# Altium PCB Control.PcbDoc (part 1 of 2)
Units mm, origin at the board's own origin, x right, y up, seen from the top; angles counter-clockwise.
Board outline 30.5 x 82 mm, 2 copper layers (Top Layer, Bottom Layer), stack 1.071 mm thick; 79 components, 65 nets, 365 pads, 467 vias.
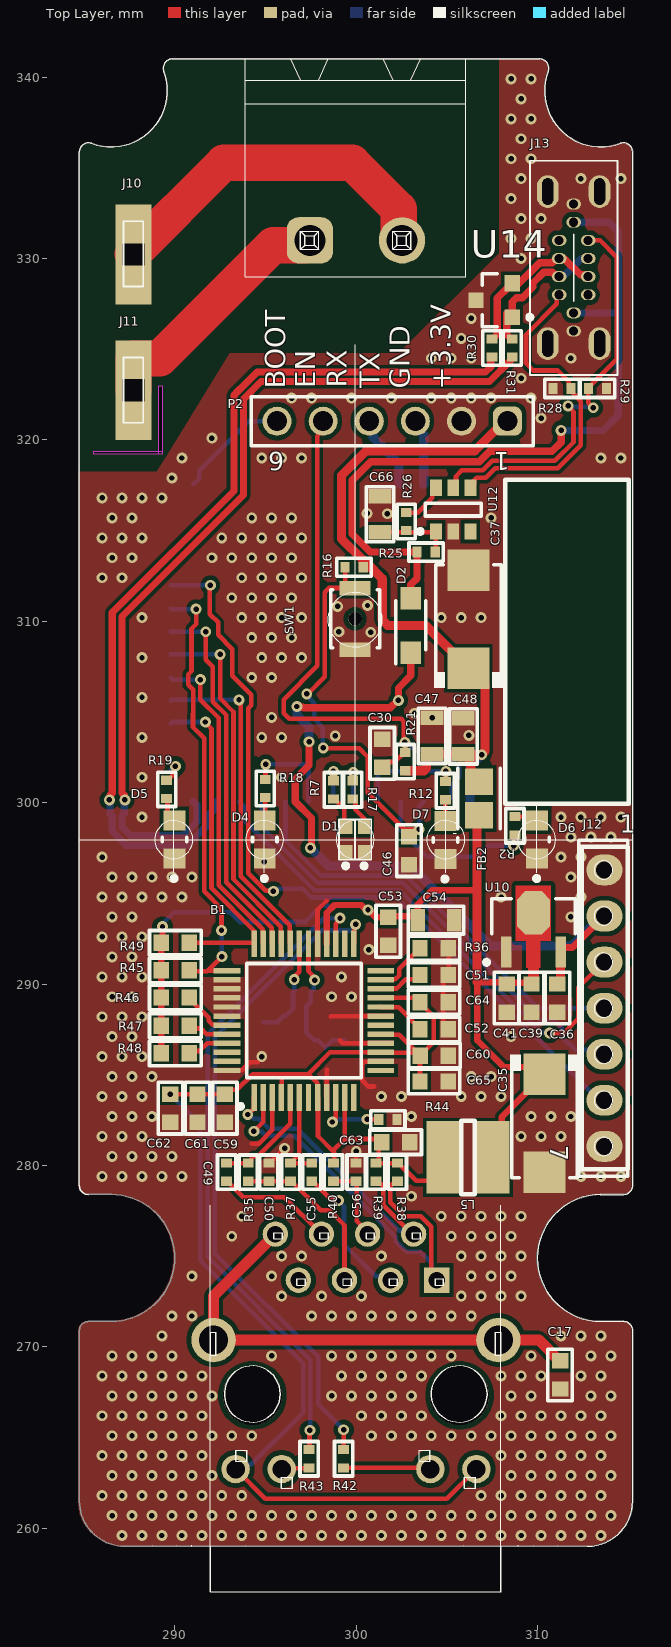
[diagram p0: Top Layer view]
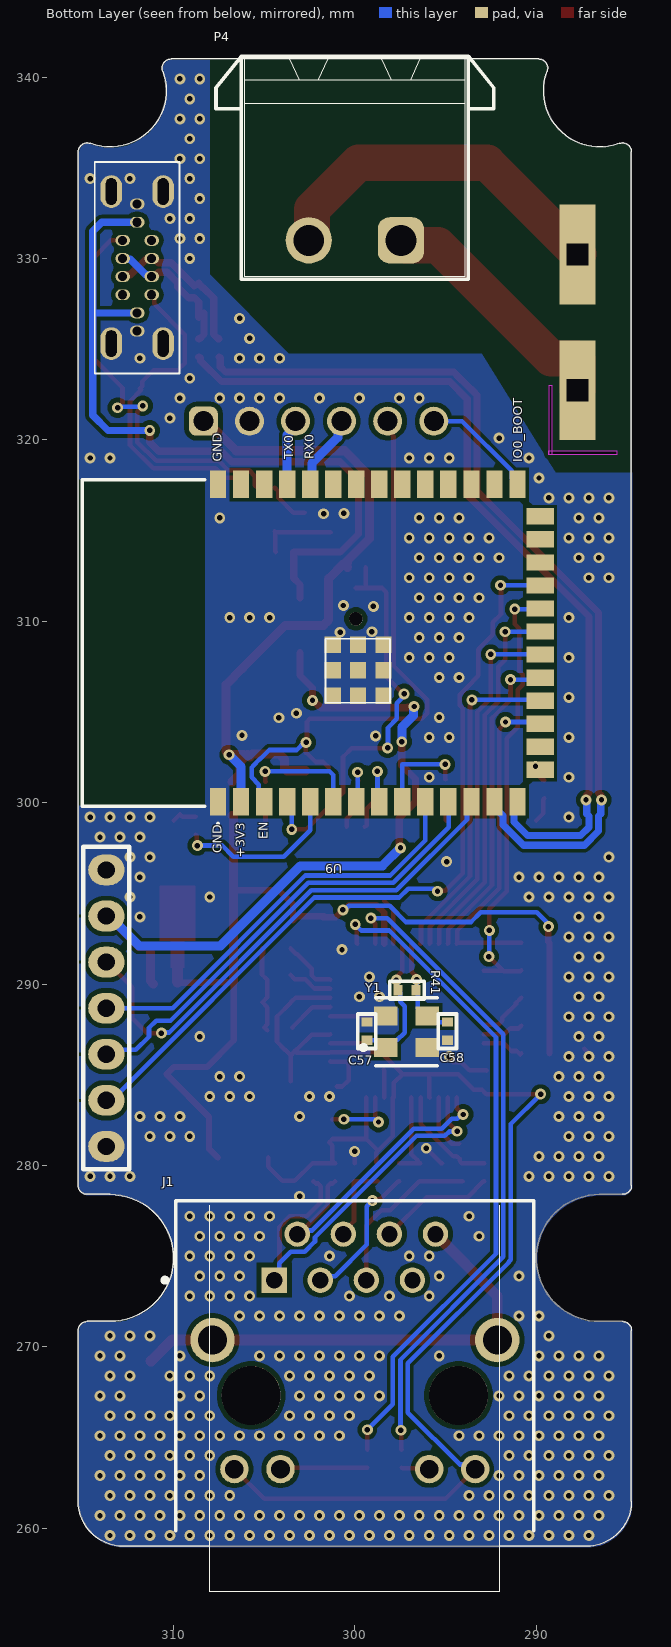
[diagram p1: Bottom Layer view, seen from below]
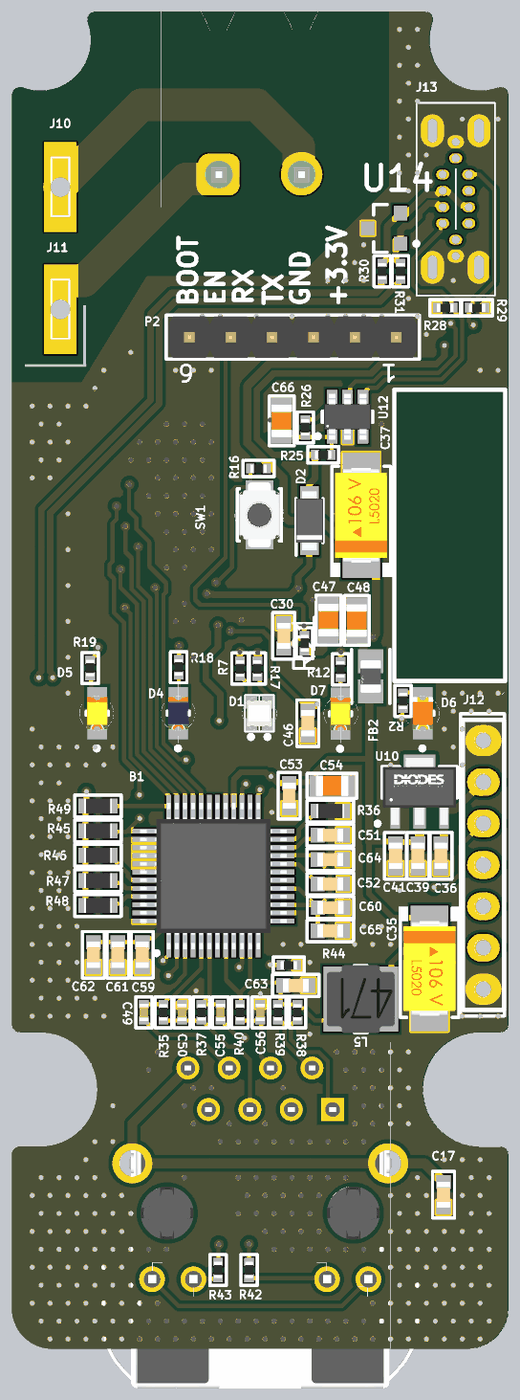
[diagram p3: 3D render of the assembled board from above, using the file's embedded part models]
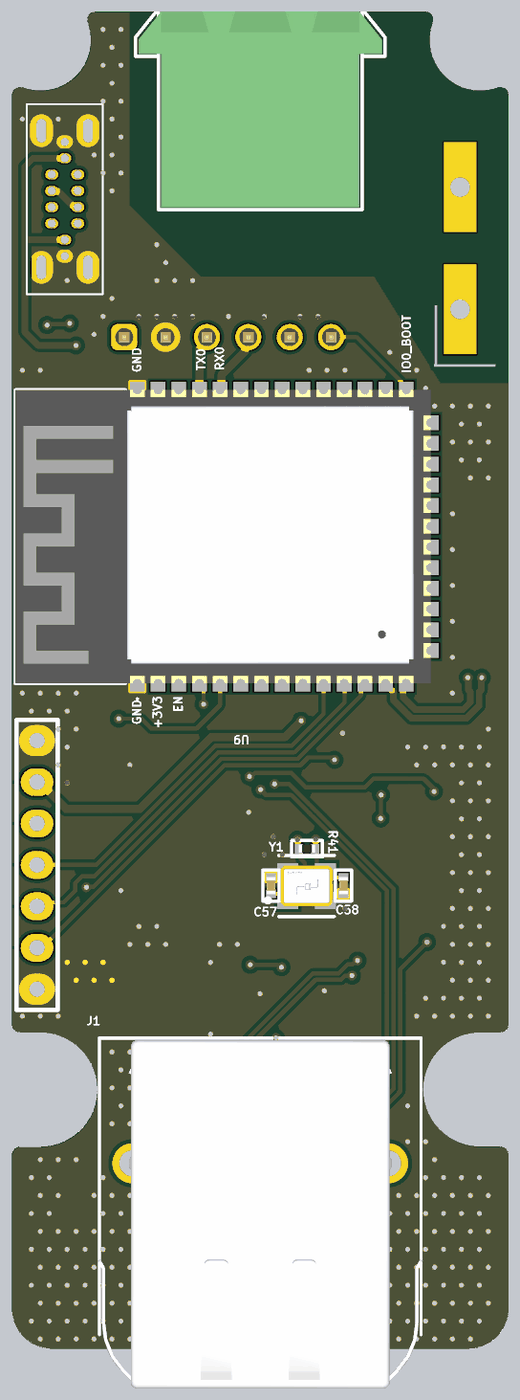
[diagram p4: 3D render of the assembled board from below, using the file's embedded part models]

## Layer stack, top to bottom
Top Solder: solder mask 0.0102, Solder Resist, Dk 3.5
Top Layer: signal copper 0.0356
Dielectric 1: dielectric 1, FR-4, Dk 4.8
Bottom Layer: signal copper 0.0356
Bottom Solder: solder mask 0.0102, Solder Resist, Dk 3.5

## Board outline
284.75,270.9 cw(c285.25,270.9) 285.25,271.4 286.5,271.4 ccw(c286.5,274.9) 286.5,278.4 285.25,278.4 cw(c285.25,278.9) 284.75,278.9 284.75,335.874 cw(c285.25,335.874) 285.424,336.343 ccw(c286.5,339.25) 289.407,340.326 cw(c289.876,340.5) 289.876,341 310.124,341 cw(c310.124,340.5) 310.593,340.326 ccw(c313.5,339.25) 314.576,336.343 cw(c314.75,335.874) 315.25,335.874 315.25,278.9 cw(c314.75,278.9) 314.75,278.4 313.5,278.4 ccw(c313.5,274.9) 313.5,271.4 314.75,271.4 cw(c314.75,270.9) 315.25,270.9 315.25,261.5 cw(c312.75,261.5) 312.75,259 287.25,259 cw(c287.25,261.5) 284.75,261.5
cut-out: 289.331,319.203 285.548,319.203 285.548,319.38 289.331,319.38
cut-out: 289.129,319.203 289.129,322.986 289.306,322.986 289.306,319.203

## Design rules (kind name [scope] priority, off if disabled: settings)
Clearance Clearance_DiffPairs [All] p1: gap=0.254 ignorepadtopadclearanceinfootprint=FALSE except(0.1: Arc-Arc Arc-Track Track-Track; 0.15: Arc-SMDPad Arc-THPad Track-SMDPad Track-THPad SMDPad-SMDPad; 0.2: Arc-Fill Arc-Poly Arc-Region Track-Fill Track-Poly Track-Region SMDPad-Fill SMDPad-Poly SMDPad-Region)
Clearance Clearance_1 [All] p2: gap=0.254 ignorepadtopadclearanceinfootprint=FALSE except(0.15: Arc-Arc Arc-Track Arc-SMDPad Arc-THPad Track-Track Track-SMDPad Track-THPad SMDPad-SMDPad; 0.2: Arc-Fill Arc-Poly Arc-Region Track-Fill Track-Poly Track-Region SMDPad-Fill SMDPad-Poly SMDPad-Region)
DiffPairsRouting DiffPairsRouting_2 [InDifferentialPair('TX')] p1: maxlimit=0.127 minlimit=0.127 mostfreqgap=0.127 toplayer_minwidth=0.257 toplayer_maxwidth=0.257 toplayer_prefwidth=0.257 bottomlayer_minwidth=0.257 bottomlayer_maxwidth=0.257 bottomlayer_prefwidth=0.257 impedanceprofiledriven=TRUE impedanceprofileid={17FF99D6-841A-44A6-B72D-4877BCBBE8D0} impedanceprofilevalue=100.000000 maxuncoupledlength=12.7
DiffPairsRouting DiffPairsRouting_1 [InDifferentialPair('D')] p2: maxlimit=0.127 minlimit=0.127 mostfreqgap=0.127 toplayer_minwidth=0.403 toplayer_maxwidth=0.403 toplayer_prefwidth=0.403 bottomlayer_minwidth=0.403 bottomlayer_maxwidth=0.403 bottomlayer_prefwidth=0.403 impedanceprofiledriven=TRUE impedanceprofileid={67F76D44-EA98-4726-9E93-E288EFCD1E18} impedanceprofilevalue=90.000000 maxuncoupledlength=12.7
DiffPairsRouting [InDifferentialPair('USB_D')] p3: maxlimit=0.127 minlimit=0.127 mostfreqgap=0.127 toplayer_minwidth=0.403 toplayer_maxwidth=0.403 toplayer_prefwidth=0.403 bottomlayer_minwidth=0.403 bottomlayer_maxwidth=0.403 bottomlayer_prefwidth=0.403 impedanceprofiledriven=TRUE impedanceprofileid={67F76D44-EA98-4726-9E93-E288EFCD1E18} impedanceprofilevalue=90.000000 maxuncoupledlength=12.7
HoleSize [All] p1: absolutevalues=TRUE maxlimit=4 minlimit=0.025 maxpercent=80.000 minpercent=20.000
Length USB_Max_Lenght [InNet('D_P')] p1: maxlimit=100 minlimit=0
MatchedLengths USB [InDifferentialPair('USB_D')] p1: tolerance=25.4 checknetsindiffpair=FALSE checkdiffpairvsdiffpair=TRUE checkxsignals=TRUE checkothers=TRUE
MinimumSolderMaskSliver [All] p1: minsoldermaskwidth=0.15
PlaneClearance [All] p1: clearance=0.25
PlaneConnect [All] p1: planeconnectstyle=Direct reliefexpansion=0.508 reliefentries=4 reliefconductorwidth=0.254 reliefairgap=0.254
PolygonConnect [All] p1: connectstyle=Direct reliefconductorwidth=0.254 reliefentries=4 polygonreliefangle="90 Angle" airgapwidth=0.254
RoutingVias [All] p1: holewidth=0.3 width=0.6 viastyle="Through Hole" minholewidth=0.3 minwidth=0.6 maxholewidth=0.4 maxwidth=0.8
SilkToSilkClearance [All] p1: silktosilkclearance=0.1
SilkToSolderMaskClearance [IsPad] p1: minsilkscreentomaskgap=0.1 clearancetoexposedcopper=TRUE
SolderMaskExpansion [All] p1: expansion=0.102 istentingtop=FALSE
SupplyNets "Schematic Supply Nets_2" [InNet('V_BUS')] p1: voltage=0.000
SupplyNets "Schematic Supply Nets_12" [InNet('G')] p2: voltage=0.000
SupplyNets "Schematic Supply Nets_11" [InNet('+3v3')] p3: voltage=0.000
SupplyNets "Schematic Supply Nets_10" [InNet('VCC_2')] p4: voltage=0.000
SupplyNets "Schematic Supply Nets_7" [InNet('+3V3_MCU')] p5: voltage=0.000
SupplyNets "Schematic Supply Nets_6" [InNet('GND_PE')] p6: voltage=0.000
Width [All] p1: maxlimit=2 minlimit=0.254 preferedwidth=0.5 minimp=50.000000 maximp=50.000000 favimp=50.000000
23 further rules are at their usual default settings.

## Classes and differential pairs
differential pair RXN: +RXN_P -RXN_N
differential pair D: +D_P -D_N
differential pair USB_D: +USB_D_P -USB_D_N
differential pair TX: +TX_P -TX_N
differential pair RX: +RX_P -RX_N

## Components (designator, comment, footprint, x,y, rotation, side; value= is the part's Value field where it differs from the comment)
B1 "W5500" QFP50P900X900X160-48N 297.129,287.985 r90 top
C17 "22nF" CAP-0603 311.252,268.453 r90 top
C30 "2.2uF" CAP-0603 301.447,302.717 r270 top
C35 "100uF 16V" CAP-TAN-C 310.388,282.321 r270 top
C36 "0.1uF" CAP-0603 311.099,289.23 r90 top
C37 "100uF_16V" CAP-TAN-C 306.2,310.109 r90 top
C39 "2.2uF" CAP-0603 309.677,289.23 r90 top
C41 "0.1uF" CAP-0603 308.305,289.23 r90 top
C46 "0.1uF" CAP-0603 302.92,297.358 r90 top
C47 "10uF" CAP-0805 304.19,303.682 r270 top
C48 "0.1uF" CAP-0805 305.918,303.657 r270 top
C49 "6.8nF" CAP-0402 292.862,279.629 r90 top
C50 "10nF" CAP-0402 295.199,279.629 r270 top
C51 "10nF" CAP-0603 304.303,290.5 r0 top locked
C52 "4.7uF" CAP-0603 304.303,287.505 r0 top locked
C53 "0.1uF" CAP-0603 301.777,292.913 r90 top
C54 "10uF" CAP-0805 304.409,293.523 r180 top
C55 "6.8nF" CAP-0402 297.561,279.629 r90 top
C56 "22nF" CAP-0402 299.999,279.629 r270 top
C57 "18pF" CAP-0402 299.339,287.401 r270 bottom
C58 "18pF" CAP-0402 294.894,287.401 r90 bottom
C59 "0.1uF" CAP-0603 292.76,283.159 r90 top
C60 "0.1uF" CAP-0603 304.317,286.055 r180 top
C61 "0.1uF" CAP-0603 291.262,283.159 r90 top
C62 "0.1uF" CAP-0603 289.763,283.159 r90 top
C63 "0.1uF" CAP-0603 302.184,281.28 r180 top
C64 "0.1uF" CAP-0603 304.303,289.001 r180 top locked
C65 "10uF" CAP-0603 304.303,284.632 r180 top locked
C66 "1uF 50V" CAP-0805 301.32,315.9 r270 top
D1 "1615 RED-GREEN" LED_Bicolor_1615 299.949,297.967 r0 top
D2 "MBR140SFT1G" SODFL3616X98N 303.022,309.778 r90 top
D4 "LED BLUE" LED_BLUE 294.97,297.967 r90 top
D5 "LED YELLOW" LED_YELLOW 289.992,297.967 r90 top
D6 "LED RED" LED_RED 309.982,297.967 r90 top
D7 "LED GREEN" LED_GREEN 304.927,297.942 r90 top
FB2 "BLM21PG221SN1D" FP-BLM21-0_2-t0_85-e0_5-IPC_A 306.781,300.228 r270 top
J1 "HR911105A" RJ-45 300,267.25 r180 bottom locked
J10 "1.2x3.7mm" Pad_conn_1.2x3.7mm#1 287.68,330.251 r90 top locked
J11 "1.2x3.7mm" Pad_conn_1.2x3.7mm#2 287.655,322.707 r90 top locked
J12 "2.54 x 7_male_25mm" 2.54_Connector_x7_male_30mm 313.7,288.671 r270 top locked
J13 "Type-C_16p" "Type-C 16p vertical" 312,329.5 r90 top locked
L5 "33uH" Coil_4.5x4.5_mm 306.172,280.441 r180 top
P2 "61300611121" 61300611121 302,321.031 r180 top
P4 "691305540002" 691305540002 300,335 r0 bottom locked
R2 "330" RES-0402 308.762,298.729 r270 top
R7 "330" RES-0402 298.755,300.711 r90 top
R12 "330" RES-0402 304.927,300.66 r90 top
R16 "10K" RES-0402 299.898,312.979 r0 top
R17 "330" RES-0402 299.822,300.711 r90 top
R18 "330" RES-0402 294.996,300.787 r90 top
R19 "330" RES-0402 289.56,300.736 r90 top
R21 "100K" RES-0402 302.717,302.26 r270 top
R25 "1K" RES-0402 303.868,313.817 r0 top
R26 "20K" RES-0402 302.768,315.493 r90 top
R28 "5.1K" RES-0402 311.353,322.834 r180 top
R29 "5.1K" RES-0402 313.309,322.834 r0 top
R30 "22R" RES-0402 307.492,325.069 r90 top
R31 "22R" RES-0402 308.61,325.069 r90 top
R35 "82R 1%" RES-0402 294.056,279.629 r270 top
R36 "10K" RES-0603 304.303,291.973 r0 top locked
R37 "82R 1%" RES-0402 296.393,279.629 r90 top
R38 "50R 1%" RES-0402 302.285,279.629 r90 top
R39 "50R 1%" RES-0402 301.092,279.629 r90 top
R40 "10R 1%" RES-0402 298.755,279.629 r270 top
R41 "1M" RES-0402 297.129,289.662 r0 bottom
R42 "510" RES-0402 299.314,263.83 r90 top
R43 "510" RES-0402 297.409,263.83 r90 top
R44 "12.4К" RES-0402 301.752,282.524 r180 top
R45 "10K" RES-0603 290.043,290.754 r0 top
R46 "10K" RES-0603 290.043,289.255 r0 top
R47 "10K" RES-0603 290.043,287.706 r0 top
R48 "10K" RES-0603 290.043,286.182 r0 top
R49 "10K" RES-0603 290.043,292.278 r0 top
SW1 "B3U-1000P" FP-B3U-1000P-B-MFG 299.949,310.134 r270 top
U9 "ESP32-S3_WROOM-1  N16R8" ESP32S3WROOM1N16R8 302.283,308.8 r90 bottom locked
U10 "AMS1117-3.3" SOT-89 309.778,293.548 r0 top
U12 "CH221K" SOT-23-6 305.359,316.154 r90 top
U14 "PESD5V0S2BT" PRKT-SOT23-3_V 307.61,327.702 r180 top
Y1 "ABM8-25.000MHZ-D1X-T" FP-ABM8 297.155,287.376 r180 bottom

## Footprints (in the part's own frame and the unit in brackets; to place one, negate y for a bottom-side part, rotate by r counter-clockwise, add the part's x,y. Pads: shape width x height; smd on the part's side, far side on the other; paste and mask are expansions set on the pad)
2.54_Connector_x7_male_30mm [mm] "2.54_Connector_x7_male_30mm"
  oval 1.7x2 hole 0.95: 1(-7.62,0) 2(-5.08,0) 3(-2.54,0) 4(0,0) 5(2.54,0) 6(5.08,0) 7(7.62,0)
  silkscreen extent -8.89,-1.27 8.89,1.27, body extent -8.89,-1.27 8.89,1.27, height 2
61300611121 [mm] "Pin Header, pitch 2.54 mm, THT, Vertical, single row, 6p"
  rrect50% 1.6x1.6 hole 1.1: 1(-6.35,0)
  round 1.6 hole 1.1: 2(-3.81,0) 3(-1.27,0) 4(1.27,0) 5(3.81,0) 6(6.35,0)
  silkscreen extent -7.77,-1.35 7.77,1.35, body extent -7.62,-1.27 7.62,1.27, height 8.57
691305540002 [mm] "5,08mm - PCB Header Horizontal Entry with Plastic Latches - 02p"
  rrect50% 2.55x2.55 hole 1.7: 1(-2.54,4)
  round 2.55 hole 1.7: 2(2.54,4)
  silkscreen extent -7.65,-6.15 7.65,6.15, body extent -7.48,-6 7.48,6, height 8.63
CAP-0402 [mm]
  rect 0.5x0.6 smd: 1(-0.5,0) 2(0.5,0)
  silkscreen extent -0.95,-0.5 0.95,0.5, body extent -0.52,-0.27 0.53,0.28, height 0.55
CAP-0603 [mm]
  rect 0.85x0.9 smd: 1(-0.775,0) 2(0.775,0)
  silkscreen extent -1.43,-0.67 1.43,0.67, body extent -0.8,-0.4 0.8,0.4, height 0.8
CAP-0805 [mm]
  rect 0.8x1.25 smd mask+0.015: 1(-1,0) 2(1,0)
  silkscreen extent -1.52,-0.76 1.52,0.76, body extent -1,-0.62 1,0.63, height 0.8
CAP-TAN-C [mm]
  rect 2.3x2.3 smd: 1(-2.7,0) 2(2.7,0)
  silkscreen extent -3.8,-1.9 3,1.9, body extent -2.9,-1.6 2.9,1.6, height 2.6
Coil_4.5x4.5_mm [mm]
  rect 1.8x4 smd: 1(-1.397,0) 2(1.397,0)
  silkscreen extent -0.38,-2.03 0.38,2.03, body extent -2.07,-2.07 2.07,2.07, height 2.8
ESP32S3WROOM1N16R8 [mm]
  rect 1.5x0.9 smd: 1(-8.75,5.26) 2(-8.75,3.99) 3(-8.75,2.72) 4(-8.75,1.45) 5(-8.75,0.18) 6(-8.75,-1.09) 7(-8.75,-2.36) 8(-8.75,-3.63) 9(-8.75,-4.9) 10(-8.75,-6.17) 11(-8.75,-7.44) 12(-8.75,-8.71) 13(-8.75,-9.98) 14(-8.75,-11.25) 27(8.75,-11.25) 28(8.75,-9.98) 29(8.75,-8.71) 30(8.75,-7.44) 31(8.75,-6.17) 32(8.75,-4.9) 33(8.75,-3.63) 34(8.75,-2.36) 35(8.75,-1.09) 36(8.75,0.18) 37(8.75,1.45) 38(8.75,2.72) 39(8.75,3.99) 40(8.75,5.26)
  rect 0.9x1.5 smd: 15(-6.985,-12.5) 16(-5.715,-12.5) 17(-4.445,-12.5) 18(-3.175,-12.5) 19(-1.905,-12.5) 20(-0.635,-12.5) 21(0.635,-12.5) 22(1.905,-12.5) 23(3.175,-12.5) 24(4.445,-12.5) 25(5.715,-12.5) 26(6.985,-12.5)
  rect 0.9x0.9 smd: 41(-1.5,-2.46) 42(-2.9,-1.06) 43(-2.9,-2.46) 44(-2.9,-3.86) 45(-1.5,-3.86) 46(-0.1,-3.86) 47(-0.1,-2.46) 48(-0.1,-1.06) 49(-1.5,-1.06)
  silkscreen extent -10,5.21 9,12.75, body extent -9,-12.75 9,12.75, height 3.25
FP-ABM8 [mm] "FP-ABM8"
  rect 1.3x1.05 smd paste+0 mask+0: 1(-1.15,-0.875) 2(1.15,-0.875) 3(1.15,0.875) 4(-1.15,0.875)
  silkscreen extent -2.5,-1.88 1.7,1.88, body extent -1.6,-1.25 1.6,1.25, height 0.8
FP-B3U-1000P-B-MFG [mm]
  rect 0.8x1.7 smd paste+0 mask+0: 1(-1.7,0) 2(1.7,0)
  round 0.75 hole 0.75 unplated paste-2539.97 mask+0: ""(0,0)
  silkscreen extent -1.6,-1.35 1.6,1.35, body extent -2.2,-1.45 2.2,1.45, height 0.25
FP-BLM21-0_2-t0_85-e0_5-IPC_A [mm]
  rect 1.455x1.556 smd paste+0 mask+0: 1(-0.926,0) 2(0.926,0)
  silkscreen extent -1.65,-1.18 1.65,1.18, body extent -1,-0.63 1,0.63, height 1.05
LED_Bicolor_1615 [mm] "LED_Bicolor_1615"
  rect 0.7x0.8 smd mask+0: 1(-0.5,0.7) 2(0.5,0.7) 3(0.5,-0.7) 4(-0.5,-0.7)
  silkscreen extent -0.89,-1.57 0.89,1.12, body extent -0.75,-0.8 0.75,0.8, height 0.55
LED_BLUE [mm]
  rect 1.1x1.2 smd paste+0 mask+0: 1(1.05,0) 2(-1.05,0)
  silkscreen extent -2.27,-0.67 0.13,0.67, body extent -1,-0.63 1,0.63, height 0.8
LED_GREEN [mm]
  rect 1.1x1.2 smd paste+0 mask+0: 1(1.05,0) 2(-1.05,0)
  silkscreen extent -2.27,-0.67 0.13,0.67, body extent -1,-0.63 1,0.63, height 0.8
LED_RED [mm]
  rect 1.1x1.2 smd paste+0 mask+0: 1(1.05,0) 2(-1.05,0)
  silkscreen extent -2.27,-0.67 0.13,0.67, body extent -1.7,-0.77 1.7,0.77, height 0.25
LED_YELLOW [mm]
  rect 1.1x1.2 smd paste+0 mask+0: 1(1.05,0) 2(-1.05,0)
  silkscreen extent -2.27,-0.67 0.13,0.67, body extent -1,-0.63 1,0.63, height 0.8
Pad_conn_1.2x3.7mm#1 [mm]
  rect 5.5x2 hole 1.2 square: 1(-0.025,-0.051)
Pad_conn_1.2x3.7mm#2 [mm]
  rect 5.5x2 hole 1.2 square: 1(0.026,-0.076)
PRKT-SOT23-3_V [mm] "SOT23, 3-Leads, Body 2.92x1.3mm, Pitch 0.94mm"
  rect 0.84x0.84 smd: 1(-1,0.94) 3(1,0)
  rect 0.84x0.9 smd: 2(-1,-0.94)
  silkscreen extent -2.09,-1.46 0.65,1.46, body extent -0.65,-1.46 0.65,1.46, height 1.17
QFP50P900X900X160-48N [mm]
  rect 1.475x0.3 smd: 1(-4.238,2.75) 2(-4.238,2.25) 3(-4.238,1.75) 4(-4.238,1.25) 5(-4.238,0.75) 6(-4.238,0.25) 7(-4.238,-0.25) 8(-4.238,-0.75) 9(-4.238,-1.25) 10(-4.238,-1.75) 11(-4.238,-2.25) 12(-4.238,-2.75) 25(4.238,-2.75) 26(4.238,-2.25) 27(4.238,-1.75) 28(4.238,-1.25) 29(4.238,-0.75) 30(4.238,-0.25) 31(4.238,0.25) 32(4.238,0.75) 33(4.238,1.25) 34(4.238,1.75) 35(4.238,2.25) 36(4.238,2.75)
  rect 0.3x1.475 smd: 13(-2.75,-4.238) 14(-2.25,-4.238) 15(-1.75,-4.238) 16(-1.25,-4.238) 17(-0.75,-4.238) 18(-0.25,-4.238) 19(0.25,-4.238) 20(0.75,-4.238) 21(1.25,-4.238) 22(1.75,-4.238) 23(2.25,-4.238) 24(2.75,-4.238) 37(2.75,4.238) 38(2.25,4.238) 39(1.75,4.238) 40(1.25,4.238) 41(0.75,4.238) 42(0.25,4.238) 43(-0.25,4.238) 44(-0.75,4.238) 45(-1.25,4.238) 46(-1.75,4.238) 47(-2.25,4.238) 48(-2.75,4.238)
  silkscreen extent -4.85,-3.15 3.15,3.62, body extent -4.5,-4.5 4.5,4.5, height 1.6
RES-0402 [mm]
  rect 0.5x0.6 smd: 1(-0.5,0) 2(0.5,0)
  silkscreen extent -0.95,-0.5 0.95,0.5, body extent -0.5,-0.25 0.5,0.25, height 0.35
RES-0603 [mm]
  rect 0.85x0.9 smd: 1(-0.775,0) 2(0.775,0)
  silkscreen extent -1.43,-0.67 1.43,0.67, body extent -0.85,-0.45 0.85,0.45, height 0.55
RJ-45 [mm] "RJ-45  connector"
  rect 1.4x1.4 hole 0.9 paste-2539.97 mask+0: 1(-4.445,6.425)
  round 1.4 hole 0.9 paste-2539.97 mask+0: 2(-3.175,8.965) 3(-1.905,6.425) 4(-0.635,8.965) 5(0.635,6.425) 6(1.905,8.965) 7(3.175,6.425) 8(4.445,8.965)
  round 1.57 hole 1.02 paste-2539.97 mask+0: 9(-6.64,-3.985) 10(-4.1,-3.985) 11(4.1,-3.985) 12(6.64,-3.985)
  round 2.45 hole 1.6 paste-2539.97 mask+0: 13(-7.85,3.125) 14(7.85,3.125)
  round 3.25 hole 3.25 unplated paste-2539.97 mask+0: ""(-5.715,0.075) ""(5.715,0.075)
  silkscreen extent -10.6,-7.37 9.87,10.8, body extent -10,-10.68 10,10.68, height 15.75
SODFL3616X98N [mm]
  rect 1.24x1.12 smd: 1(-1.5,0) 2(1.5,0)
  silkscreen extent -2.12,-0.82 1.35,0.82, body extent -1.8,-0.82 1.8,0.82, height 0.98
SOT-23-6 [mm] "SOT-23-6"
  rect 0.9x0.65 smd: 1(-1.2,0.95) 2(-1.2,0) 3(-1.2,-0.95) 4(1.2,-0.95) 5(1.2,0) 6(1.2,0.95)
  silkscreen extent -1.32,-1.55 0.35,1.95, body extent -1.4,-1.45 1.4,1.45, height 1.2
SOT-89 [mm]
  rect 0.58x1.73 smd paste+0 mask+0: 1(-1.5,-1.781) 3(1.5,-1.781)
  oct 1.827x2.394 smd paste+0 mask+0: 2(0,0.381)
  Top Layer region: -0.38,-2.646 -0.38,-1.146 -0.967,-1.146 -0.967,1.884 0.967,1.884 0.967,-1.146 0.38,-1.146 0.38,-2.646
  silkscreen extent -2.7,-2.47 2.3,1.15, body extent -2.4,-2.75 2.4,1.98, height 0.25
"Type-C 16p vertical" [mm] "Type-C 16p vertical"
  oval 0.6x0.8 hole 0.5: A1/B12(-3.5,0) A4/B9(-2.5,0) A5(-1.5,0.8) A6(-0.5,0.8) A7(0.5,0.8) A8(1.5,0.8) A12/B1(3.5,0) B4/A9(2.5,0) B5(1.5,-0.8) B6(0.5,-0.8) B7(-0.5,-0.8) B8(-1.5,-0.8)
  oval 1.8x1.2 hole 0.6 slot 1.462 at 0 deg: MNT1(-4.191,1.43) MNT2(-4.191,-1.43) MNT3(4.191,-1.43) MNT4(4.191,1.43)
  silkscreen extent -5.92,-2.41 5.89,2.41, body extent -6,-2.5 6,2.5, height 13.7

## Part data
B1: "Ethernet ICs 3in1 Enet Controller TCP/IP +MAC+PHY", Manufacturer_Name="Wiznet Technology"
C17 C30 C39 C41 C46 C47 C48 C49 C50 C51 C52 C53 C54 C55 C56 C57 C58 C59 C60 C61 C62 C63 C64 C65 C66: library part CAP-NON-POLAR
C35: library part CAP-POLAR, "100uF 16V  size-C"
C36: library part CAP-NON-POLAR, "0.1uF 16V"
C37: library part CAP_POL_SMD, "100uF_16V  size-C"
D1: library part "LED Bicolor", "1615 bicolor SMD LED 2 colors Red+GREEN /  / DY-S161506URUGC-T10-4T-03"
D2: "MBR140SFT1G / DIODE SCHOTTKY 40V 1A SOD123L"
D4: library part LED, "XL-2012UBC XINGLIGHT 0805 LED BLUE", Manufacturer_Name="Wurth Elektronik", Manufacturer_Part_Number=151031YS06000, Mouser Part Number=710-151031YS06000
D5: library part LED, "XL-2012UYC  XINGLIGHT 0805 LED YELLOW", Manufacturer_Name="Wurth Elektronik", Manufacturer_Part_Number=151031YS06000, Mouser Part Number=710-151031YS06000
D6: library part LED, "XL-2012SURC   XINGLIGHT  0805  LED RED", Manufacturer_Name="Wurth Elektronik", Manufacturer_Part_Number=151031YS06000, Mouser Part Number=710-151031YS06000
D7: library part LED, "XL-2012SYGC-06  XINGLIGHT  0805  LED GREEN", Manufacturer_Name="Wurth Elektronik", Manufacturer_Part_Number=151031YS06000, Mouser Part Number=710-151031YS06000
FB2: "Chip Ferrite Bead, 0805, 220Ω @ 100MHz, 0.045Ω, 25%, 2A"
J1: library part HRK1-1B72F09
J10 J11: library part Klema_15_A
J12: library part 2.54_Connector_x7_male_25mm, "2.54_Connector_x7_male_25mm"
J13: "Type-C_16p  TYPE-C16P female socket vertical plug-in patch 8.8 mm  /  / https://www.aliexpress.com/item/1005012731556882.html?spm=a2g0o.cart.0.0.a5d038da7FoSd6&mp=1&pdp_npi=6%40dis%21UAH%21UAH+257.01%21UAH+231.29%21%21UAH+223.44%21%21%21%402103842a17955063158303339e1049%2112000059158355455%21ct%21UA%214339914066%21%211%210%21"
L5: library part Coil
P2: "WR-PHD Pin Header, THT, Vertical, pitch 2.54mm, 1 Row, 6P", Contact Resistance=20mΩ, Manufacturer="Wurth Elektronik", Operating Temperature Max=105°C, Operating Temperature Min=-40°C, Rated Current=3A, Withstanding Voltage=500V, Working Voltage=250V
P4: "WR-TBL Series 3055 PCB Header Horizontal Entry with Plastic Latches, THT, pitch 5.08mm, 02p", Manufacturer="Wurth Elektronik", Operating Temperature Max=105degC, Operating Temperature Min=-40degC, Rated Current=16A, Working Voltage="300V (AC)"
R2 R7 R12 R16 R17 R18 R19 R21 R25 R26 R28 R29 R30 R31 R35 R36 R37 R38 R39 R40 R41 R42 R43 R45 R46 R47 R48 R49: library part RES-CONST
R44: library part RES-CONST, "12.4К  1%"
U9: library part "ESP32-S3_WROOM-1 N16R8", "ESP32-S3_WROOM-1 N16R8"
U10: library part AMS1117
U12: "WCH CH221K /  / https://www.lcsc.com/product-detail/C5125736.html?s_z=n_q_x_CH221K&spm=wm.ssy.em.0.tz&lcsc_vid=T1ILBVxSEgBWUlIFElIIVl1eEgJYAVZUQVBaAlBUQVExVlNfQlRfXlNXQ1JfUTsOAxUeFF5JWBYZEEoKFBINSQcJGk4NBhADEA4cHktXRlVeSQwSGg0%3D"
U14: library part CMP-2000-07553-1, "TVS Array - Low capacitance bidirectional double ESD protection diode / https://www.lcsc.com/product-detail/C49338.html?s_z=n_q_PESD5V0S2BT&spm=wm.fly.bg.0.xh&lcsc_vid=T1ILBVxSEgBWUlIFElIIVl1eEgJYAVZUQVBaAlBUQVExVlNfQldfUFRWQVRbVDsOAxUeFF5JWBYZEEoKFBINSQcJGk4NBhADEA4cHktRR1NADxALGw%3D%3D", Capacitance=75pF, Case\/Package=SOT-23, Clamping Voltage=17V, Current=20uA, Manufacturer="Protek Devices", Max Operating Temperature=150degC, Min Breakdown Voltage=7.5V, Min Operating Temperature=-55degC, Package Description="3-Pin Small Outline Transistor, Body 2.92 x 1.3 mm, Pitch 0.94 mm", Package Reference=SOT23-3, Power Dissipation=600W, Voltage=12V, Working Voltage=7V
Y1: library part ABM8-25.000MHZ, "Crystal 25MHz ±10ppm 18pF SMD-4 3.2mm x 2.5mm"

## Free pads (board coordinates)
  round 0.006 on Top Overlay: 1(284.691,261.523) 1(284.691,261.523) 1(284.691,270.923) 1(284.691,270.923) 1(284.693,261.525) 1(284.693,261.525) 1(284.693,270.925) 1(284.693,270.925) 1(284.716,270.923) 1(284.716,270.923) 1(284.716,278.923) 1(284.716,278.923) 1(285.191,278.423) 1(285.191,278.423) 1(285.193,278.425) 1(285.193,278.425) 1(285.216,278.423) 1(285.216,278.423) 1(286.441,271.423) 1(286.441,271.423) 1(286.443,271.425) 1(286.443,271.425) 1(286.466,271.423) 1(286.466,271.423) 1(288.792,259.004) 1(289.348,340.35) 1(289.348,340.35) 1(289.35,340.351) 1(289.35,340.351) 1(289.373,340.35) 1(289.373,340.35) 1(290.117,259.004) 1(290.961,259.004) 1(291.941,259.023) 1(291.943,259.025) 1(291.966,259.023) 1(293.961,259.004) 1(305.961,259.004) 1(307.941,259.023) 1(307.943,259.025) 1(307.966,259.023) 1(308.961,259.004) 1(309.805,259.004) 1(311.133,259.004) 1(313.441,278.423) 1(313.441,278.423) 1(313.443,278.425) 1(313.443,278.425) 1(313.466,278.423) 1(313.466,278.423) 1(314.517,336.366) 1(314.517,336.366) 1(314.519,336.367) 1(314.519,336.367) 1(314.543,336.366) 1(314.543,336.366) 1(315.191,278.923) 1(315.191,278.923) 1(315.193,278.925) 1(315.193,278.925)
  round 0.1 on Top Overlay: 1(312.288,279.405) 1(312.288,279.405) 1(312.288,297.935) 1(312.288,297.935) 1(314.988,279.405) 1(314.988,279.405) 1(314.988,297.935) 1(314.988,297.935)

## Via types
v1: diameter 0.6, hole 0.3, Top Layer to Bottom Layer, tented both sides, 467 vias

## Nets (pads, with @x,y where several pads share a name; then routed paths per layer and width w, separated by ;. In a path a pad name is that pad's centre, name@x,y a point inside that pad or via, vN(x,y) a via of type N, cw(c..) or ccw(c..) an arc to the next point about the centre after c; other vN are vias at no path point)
+3v3: B1.28 C35.1 C39.2 C41.2 C53.2 C54.2 FB2.2 L5.1 R45.1 R46.1 R47.1 R48.1 R49.1 U10.2 | length 61
  Top Layer w0.35: R48.1@289.268,286.182 R47.1@289.268,287.706 R46.1@289.268,289.255 R45.1@289.268,290.754 R49.1@289.268,292.278 289.331,292.342 v1(289.331,293.167) ; B1.28@298.379,292.223 298.379,293.858 298.389,293.868 298.389,293.935 298.816,294.362 300.295,294.362 300.441,294.216 300.467,294.216 300.592,294.091 v1(300.66,294.091) 301.063,293.688 C53.2@301.777,293.688 ; C53.2@301.693,293.747 303.184,293.747 C54.2@303.409,293.522 303.409,294.392 304.19,295.173 306.68,295.173 ; L5.1@307.569,280.441 308.041,280.913 308.041,282.674 C35.1@310.388,285.021 309.982,285.427 308.145,285.427 306.68,286.893 306.68,290.106 308.204,290.106 C41.2@308.305,290.005 308.381,290.081 309.601,290.081 C39.2@309.677,290.005 C39.2@309.778,290.106
  Top Layer w0.5: 306.68,290.106 306.68,295.173 306.68,299.201 FB2.2@306.781,299.302
  Top Layer w0.6: C39.2@309.778,290.106 U10.2@309.778,293.929
  Bottom Layer w0.254: v1(289.331,293.167) 289.331,293.319 289.966,293.954 293.065,293.954 293.599,293.421 297.188,293.421 298.082,294.314 300.343,294.314 300.566,294.091 v1(300.66,294.091)
+3V3_MCU: C37.1 C47.2 C48.2 FB2.1 P2.1 R16.2 R21.2 U9.2 | length 40.2
  Top Layer w0.5: R16.2@300.398,312.979 300.605,313.186 301.447,312.344 301.447,310.071 301.74,309.778 303.83,309.778 C37.1@306.2,307.409 307.1,306.509 307.1,306.227 307.111,306.216 307.111,302.846 306.934,302.668 v1(306.934,302.641) 306.553,302.641 ; R16.2@300.398,313.226 300.398,313.357 299.196,314.559 299.196,318.03 300.567,319.401 306.546,319.401 307.626,320.481 307.719,320.481 308.269,321.031 P2.1@308.35,321.031 ; R21.2@302.717,301.76 303.737,301.76 303.886,301.909 303.886,302.409 304.159,302.682 C47.2@304.191,302.682 C48.2@305.654,302.682 ; C48.2@305.791,302.53 C48.2@305.918,302.657 306.324,302.251 306.324,301.899 306.329,301.893 306.329,301.606 FB2.1@306.781,301.154 ; C48.2@306.105,302.641 306.553,302.641 ; C48.2@306.299,302.387 306.553,302.641
  Bottom Layer w0.5: U9.2@306.273,300.05 306.273,301.981 v1(306.934,302.641)
D_N: J13.A7 J13.B7 R30.2 U14.2 | length 8.7
  Top Layer w0.403: R30.2@307.492,325.569 307.542,325.569 307.786,325.813 307.786,327.819 308.361,328.393 308.391,328.393 308.61,328.612 U14.2@308.61,328.642 ; U14.2@308.851,328.491 310.125,329.765 310.811,329.765 311.047,330 J13.A7@311.2,330 311.238,329.962 311.515,329.962 312.378,329.099 312.548,329.099 312.609,329.038 312.883,329.038 J13.B7@312.91,329.065
D_P: J13.A6 J13.B6 R31.2 U14.1 | length 7.9
  Top Layer w0.403: U14.1@308.316,326.981 308.316,325.813 308.56,325.569 R31.2@308.61,325.569 ; U14.1@308.61,326.762 308.61,327.605 308.845,327.841 309.175,327.841 309.76,328.425 309.76,328.65 310.345,329.235 310.811,329.235 311.047,329 J13.A6@311.2,329
  Bottom Layer w0.403: J13.A6@311.2,329 311.353,329 311.452,329.099 311.522,329.099 312.385,329.962 312.762,329.962 J13.B6@312.8,330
